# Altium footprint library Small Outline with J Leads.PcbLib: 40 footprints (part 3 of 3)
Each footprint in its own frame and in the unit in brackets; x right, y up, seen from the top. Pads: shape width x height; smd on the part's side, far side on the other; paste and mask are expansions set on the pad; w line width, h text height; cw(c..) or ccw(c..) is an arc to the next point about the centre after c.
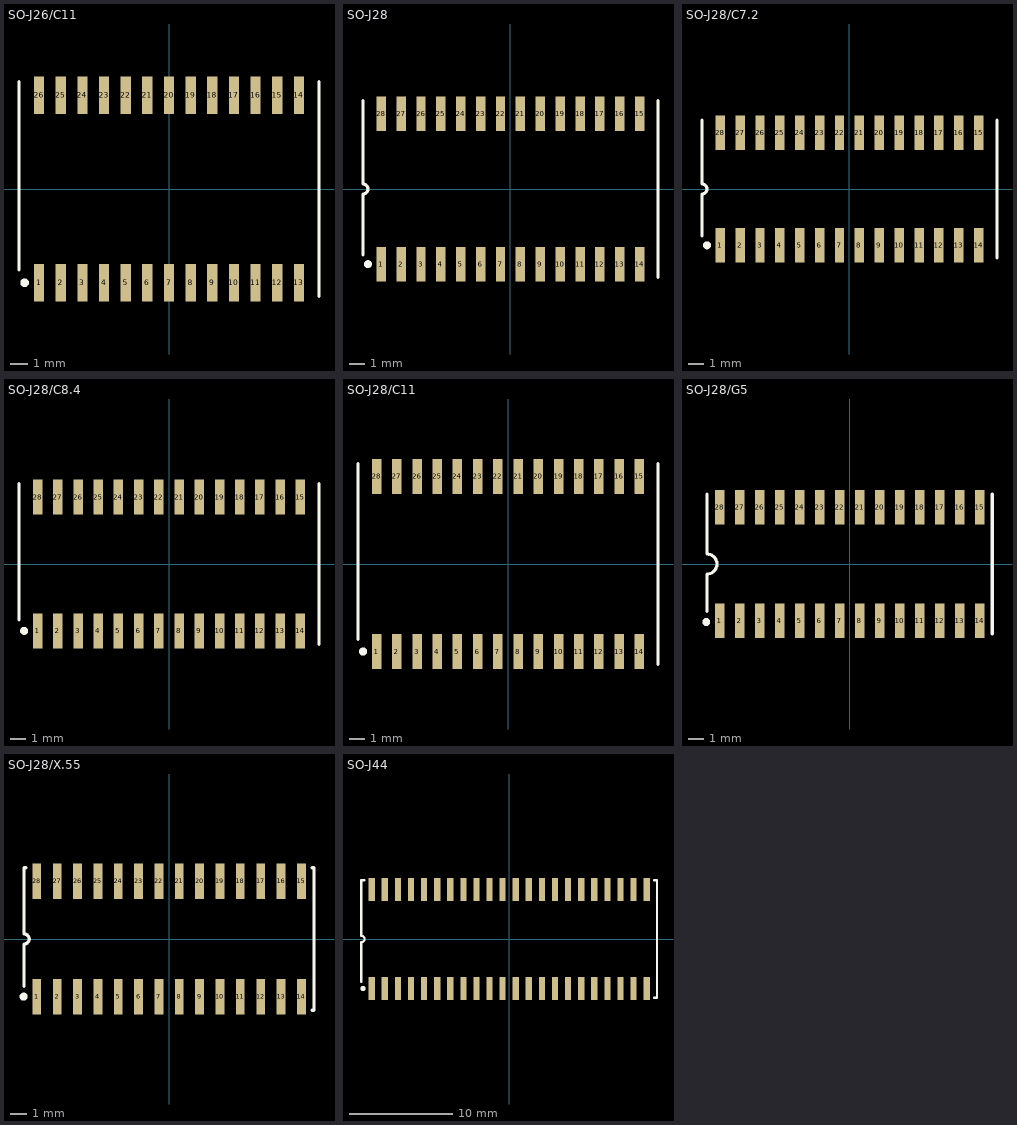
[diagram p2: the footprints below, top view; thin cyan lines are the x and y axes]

## SO-J26/C11 [mm]
pads (26):
  rect 0.6x2.2 smd: 1(-7.62,-5.5) 2(-6.35,-5.5) 3(-5.08,-5.5) 4(-3.81,-5.5) 5(-2.54,-5.5) 6(-1.27,-5.5) 7(0,-5.5) 8(1.27,-5.5) 9(2.54,-5.5) 10(3.81,-5.5) 11(5.08,-5.5) 12(6.35,-5.5) 13(7.62,-5.5) 14(7.62,5.5) 15(6.35,5.5) 16(5.08,5.5) 17(3.81,5.5) 18(2.54,5.5) 19(1.27,5.5) 20(0,5.5) 21(-1.27,5.5) 22(-2.54,5.5) 23(-3.81,5.5) 24(-5.08,5.5) 25(-6.35,5.5) 26(-7.62,5.5)
Top Overlay:
  circle w0.25: c-8.47,-5.5 r0.125
  lines w0.2: -8.8,-4.75 -8.8,6.3 ; 8.8,-6.3 8.8,6.3

## SO-J28 [mm]
pads (28):
  rect 0.6x2.2 smd: 1(-8.255,-4.8) 2(-6.985,-4.8) 3(-5.715,-4.8) 4(-4.445,-4.8) 5(-3.175,-4.8) 6(-1.905,-4.8) 7(-0.635,-4.8) 8(0.635,-4.8) 9(1.905,-4.8) 10(3.175,-4.8) 11(4.445,-4.8) 12(5.715,-4.8) 13(6.985,-4.8) 14(8.255,-4.8) 15(8.255,4.8) 16(6.985,4.8) 17(5.715,4.8) 18(4.445,4.8) 19(3.175,4.8) 20(1.905,4.8) 21(0.635,4.8) 22(-0.635,4.8) 23(-1.905,4.8) 24(-3.175,4.8) 25(-4.445,4.8) 26(-5.715,4.8) 27(-6.985,4.8) 28(-8.255,4.8)
Top Overlay:
  circle w0.25: c-9.105,-4.8 r0.125
  lines w0.2: -9.425,-4.2 -9.425,-0.318 ccw(c-9.425,0) -9.425,0.318 -9.425,5.65 ; 9.425,-5.65 9.425,5.65

## SO-J28/C7.2 [mm]
pads (28):
  rect 0.6x2.2 smd: 1(-8.255,-3.6) 2(-6.985,-3.6) 3(-5.715,-3.6) 4(-4.445,-3.6) 5(-3.175,-3.6) 6(-1.905,-3.6) 7(-0.635,-3.6) 8(0.635,-3.6) 9(1.905,-3.6) 10(3.175,-3.6) 11(4.445,-3.6) 12(5.715,-3.6) 13(6.985,-3.6) 14(8.255,-3.6) 15(8.255,3.6) 16(6.985,3.6) 17(5.715,3.6) 18(4.445,3.6) 19(3.175,3.6) 20(1.905,3.6) 21(0.635,3.6) 22(-0.635,3.6) 23(-1.905,3.6) 24(-3.175,3.6) 25(-4.445,3.6) 26(-5.715,3.6) 27(-6.985,3.6) 28(-8.255,3.6)
Top Overlay:
  circle w0.25: c-9.105,-3.6 r0.125
  lines w0.2: -9.425,-3 -9.425,-0.318 ccw(c-9.425,0) -9.425,0.318 -9.425,4.4 ; 9.425,-4.4 9.425,4.4

## SO-J28/C8.4 [mm]
pads (28):
  rect 0.6x2.2 smd: 1(-8.255,-4.2) 2(-6.985,-4.2) 3(-5.715,-4.2) 4(-4.445,-4.2) 5(-3.175,-4.2) 6(-1.905,-4.2) 7(-0.635,-4.2) 8(0.635,-4.2) 9(1.905,-4.2) 10(3.175,-4.2) 11(4.445,-4.2) 12(5.715,-4.2) 13(6.985,-4.2) 14(8.255,-4.2) 15(8.255,4.2) 16(6.985,4.2) 17(5.715,4.2) 18(4.445,4.2) 19(3.175,4.2) 20(1.905,4.2) 21(0.635,4.2) 22(-0.635,4.2) 23(-1.905,4.2) 24(-3.175,4.2) 25(-4.445,4.2) 26(-5.715,4.2) 27(-6.985,4.2) 28(-8.255,4.2)
Top Overlay:
  circle w0.25: c-9.105,-4.2 r0.125
  lines w0.2: -9.425,-3.5 -9.425,5.05 ; 9.425,-5.05 9.425,5.05

## SO-J28/C11 [mm]
pads (28):
  rect 0.6x2.2 smd: 1(-8.255,-5.5) 2(-6.985,-5.5) 3(-5.715,-5.5) 4(-4.445,-5.5) 5(-3.175,-5.5) 6(-1.905,-5.5) 7(-0.635,-5.5) 8(0.635,-5.5) 9(1.905,-5.5) 10(3.175,-5.5) 11(4.445,-5.5) 12(5.715,-5.5) 13(6.985,-5.5) 14(8.255,-5.5) 15(8.255,5.5) 16(6.985,5.5) 17(5.715,5.5) 18(4.445,5.5) 19(3.175,5.5) 20(1.905,5.5) 21(0.635,5.5) 22(-0.635,5.5) 23(-1.905,5.5) 24(-3.175,5.5) 25(-4.445,5.5) 26(-5.715,5.5) 27(-6.985,5.5) 28(-8.255,5.5)
Top Overlay:
  circle w0.25: c-9.105,-5.5 r0.125
  lines w0.2: -9.425,-4.75 -9.425,6.3 ; 9.425,-6.3 9.425,6.3

## SO-J28/G5 [mm]
pads (28):
  rect 0.6x2.2 smd: 1(-8.255,-3.6) 2(-6.985,-3.6) 3(-5.715,-3.6) 4(-4.445,-3.6) 5(-3.175,-3.6) 6(-1.905,-3.6) 7(-0.635,-3.6) 8(0.635,-3.6) 9(1.905,-3.6) 10(3.175,-3.6) 11(4.445,-3.6) 12(5.715,-3.6) 13(6.985,-3.6) 14(8.255,-3.6) 15(8.255,3.6) 16(6.985,3.6) 17(5.715,3.6) 18(4.445,3.6) 19(3.175,3.6) 20(1.905,3.6) 21(0.635,3.6) 22(-0.635,3.6) 23(-1.905,3.6) 24(-3.175,3.6) 25(-4.445,3.6) 26(-5.715,3.6) 27(-6.985,3.6) 28(-8.255,3.6)
Top Overlay:
  circle w0.25: c-9.105,-3.68 r0.125
  lines w0.2: -9.055,-3 -9.055,-0.639 ccw(c-9.055,-0.004) -9.055,0.631 -9.055,4.45 ; 9.055,-4.45 9.055,4.45

## SO-J28/X.55 [mm]
pads (28):
  rect 0.55x2.2 smd: 1(-8.255,-3.6) 2(-6.985,-3.6) 3(-5.715,-3.6) 4(-4.445,-3.6) 5(-3.175,-3.6) 6(-1.905,-3.6) 7(-0.635,-3.6) 8(0.635,-3.6) 9(1.905,-3.6) 10(3.175,-3.6) 11(4.445,-3.6) 12(5.715,-3.6) 13(6.985,-3.6) 14(8.255,-3.6) 15(8.255,3.6) 16(6.985,3.6) 17(5.715,3.6) 18(4.445,3.6) 19(3.175,3.6) 20(1.905,3.6) 21(0.635,3.6) 22(-0.635,3.6) 23(-1.905,3.6) 24(-3.175,3.6) 25(-4.445,3.6) 26(-5.715,3.6) 27(-6.985,3.6) 28(-8.255,3.6)
Top Overlay:
  circle w0.25: c-9.08,-3.6 r0.125
  lines w0.2: -9.05,-2.95 -9.05,-0.318 ccw(c-9.05,0) -9.05,0.318 -9.05,4.45 -8.93,4.45 ; 8.93,-4.45 9.05,-4.45 9.05,4.45 8.93,4.45

## SO-J44 [mm]
pads (44):
  rect 0.6x2.2 smd: 1(-13.335,-4.8) 2(-12.065,-4.8) 3(-10.795,-4.8) 4(-9.525,-4.8) 5(-8.255,-4.8) 6(-6.985,-4.8) 7(-5.715,-4.8) 8(-4.445,-4.8) 9(-3.175,-4.8) 10(-1.905,-4.8) 11(-0.635,-4.8) 12(0.635,-4.8) 13(1.905,-4.8) 14(3.175,-4.8) 15(4.445,-4.8) 16(5.715,-4.8) 17(6.985,-4.8) 18(8.255,-4.8) 19(9.525,-4.8) 20(10.795,-4.8) 21(12.065,-4.8) 22(13.335,-4.8) 23(13.335,4.8) 24(12.065,4.8) 25(10.795,4.8) 26(9.525,4.8) 27(8.255,4.8) 28(6.985,4.8) 29(5.715,4.8) 30(4.445,4.8) 31(3.175,4.8) 32(1.905,4.8) 33(0.635,4.8) 34(-0.635,4.8) 35(-1.905,4.8) 36(-3.175,4.8) 37(-4.445,4.8) 38(-5.715,4.8) 39(-6.985,4.8) 40(-8.255,4.8) 41(-9.525,4.8) 42(-10.795,4.8) 43(-12.065,4.8) 44(-13.335,4.8)
Top Overlay:
  circle w0.25: c-14.185,-4.8 r0.125
  lines w0.2: -14.35,-4.15 -14.35,-0.317 ccw(c-14.35,0) -14.35,0.318 -14.35,5.7 -14.035,5.7 ; 14.035,-5.7 14.35,-5.7 14.35,5.7 14.035,5.7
